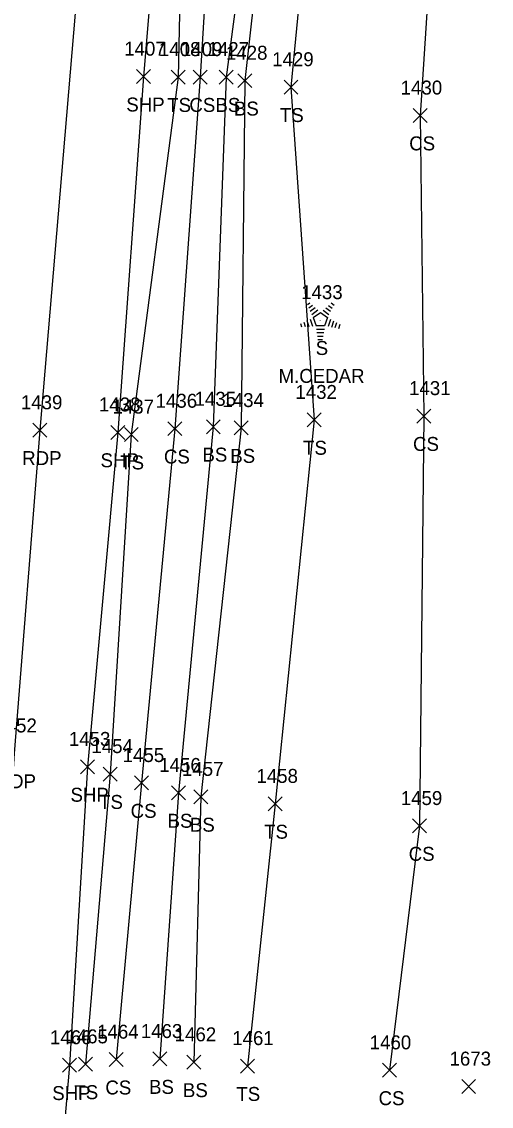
# Model space of a CAD drawing. Extents: x 1443960 to 1446865, y 610387 to 616706.
# Drawn here: x 1446592.3 to 1446659.6, y 610855.3 to 611010.8 of the extents above; entities that cross this region are included whole.
import ezdxf

# ---------------------------------------------------------------- set-up
doc = ezdxf.new("R2010")
doc.units = 0
for name, color, linetype in [('L_A', 7, 'Continuous'), ('L_C', 7, 'Continuous'), ('L_I', 7, 'Continuous'), ('L_TIC', 7, 'Continuous'), ('LELB', 7, 'Continuous'), ('LTC', 7, 'Continuous'), ('P_A', 7, 'Continuous'), ('P_I', 7, 'Continuous'), ('P_TIC', 7, 'Continuous'), ('PET', 7, 'Continuous'), ('PSP', 7, 'Continuous')]:
    doc.layers.add(name, color=color, linetype=linetype)

msp = doc.modelspace()

# ---------------------------------------------------------------- linework, layer by layer
at = {"layer": 'L_TIC'}
for points in [[(1446613.77, 611001.83), (1446615.77, 611003.83)], [(1446615.77, 611001.83), (1446613.77, 611003.83)], [(1446616.92, 611001.83), (1446618.92, 611003.83)], [(1446618.92, 611001.83), (1446616.92, 611003.83)], [(1446620.65, 611001.83), (1446622.65, 611003.83)], [(1446622.65, 611001.83), (1446620.65, 611003.83)], [(1446623.29, 611001.31), (1446625.29, 611003.31)], [(1446625.29, 611001.31), (1446623.29, 611003.31)], [(1446629.92, 611000.38), (1446631.92, 611002.38)], [(1446631.92, 611000.38), (1446629.92, 611002.38)], [(1446648.42, 610996.32), (1446650.42, 610998.32)], [(1446650.42, 610996.32), (1446648.42, 610998.32)], [(1446633.24, 610952.7), (1446635.24, 610954.7)], [(1446635.24, 610952.7), (1446633.24, 610954.7)], [(1446648.97, 610953.25), (1446650.97, 610955.25)], [(1446650.97, 610953.25), (1446648.97, 610955.25)], [(1446613.27, 610951.44), (1446615.27, 610953.44)], [(1446615.27, 610951.44), (1446613.27, 610953.44)], [(1446618.79, 610951.72), (1446620.79, 610953.72)], [(1446620.79, 610951.72), (1446618.79, 610953.72)], [(1446622.78, 610951.54), (1446624.78, 610953.54)], [(1446624.78, 610951.54), (1446622.78, 610953.54)], [(1446607.04, 610950.6), (1446609.04, 610952.6)], [(1446609.04, 610950.6), (1446607.04, 610952.6)], [(1446604.01, 610901.95), (1446606.01, 610903.95)], [(1446606.01, 610901.95), (1446604.01, 610903.95)], [(1446608.49, 610900.67), (1446610.49, 610902.67)], [(1446610.49, 610900.67), (1446608.49, 610902.67)], [(1446613.79, 610899.25), (1446615.79, 610901.25)], [(1446615.79, 610899.25), (1446613.79, 610901.25)], [(1446616.99, 610898.69), (1446618.99, 610900.69)], [(1446618.99, 610898.69), (1446616.99, 610900.69)], [(1446627.67, 610897.68), (1446629.67, 610899.68)], [(1446629.67, 610897.68), (1446627.67, 610899.68)], [(1446648.35, 610894.51), (1446650.35, 610896.51)], [(1446650.35, 610894.51), (1446648.35, 610896.51)], [(1446604.88, 610861.03), (1446606.88, 610863.03)], [(1446606.88, 610861.03), (1446604.88, 610863.03)], [(1446611.14, 610861.12), (1446613.14, 610863.12)], [(1446613.14, 610861.12), (1446611.14, 610863.12)], [(1446600.47, 610860.36), (1446602.47, 610862.36)], [(1446602.47, 610860.36), (1446600.47, 610862.36)], [(1446615.99, 610860.65), (1446617.99, 610862.65)], [(1446617.99, 610860.65), (1446615.99, 610862.65)], [(1446623.68, 610860.11), (1446625.68, 610862.11)], [(1446625.68, 610860.11), (1446623.68, 610862.11)], [(1446644.03, 610859.5), (1446646.03, 610861.5)], [(1446646.03, 610859.5), (1446644.03, 610861.5)], [(1446655.38, 610857.17), (1446657.38, 610859.17)], [(1446657.38, 610857.17), (1446655.38, 610859.17)]]:
    msp.add_lwpolyline(points, dxfattribs=at)
at = {"layer": 'LELB'}
for points in [[(1446830.28, 611016.53), (1446811.1, 611028.66), (1446776.07, 611047.22), (1446765.1, 611052.74), (1446718.13, 611075.14), (1446677.7, 611094.8), (1446645.56, 611110.93), (1446633.09, 611119.85), (1446623.05, 611121.28), (1446619.75, 611099.3), (1446617.85, 611081.96), (1446615.6, 611043.86), (1446614.77, 611002.83), (1446608.04, 610951.6), (1446605.01, 610902.95), (1446601.47, 610861.36)], [(1446829.25, 611014.38), (1446810.48, 611025.97), (1446776.26, 611044.05), (1446764.8, 611049.49), (1446716.62, 611070.84), (1446676.65, 611091.11), (1446643.97, 611105.98), (1446632.65, 611089.9), (1446628.97, 611091.61), (1446629.07, 611084.29), (1446632.07, 611081.47), (1446632.15, 611079.98), (1446631.66, 611078.24), (1446628.85, 611073.01), (1446626.96, 611043.36), (1446621.65, 611002.83), (1446619.79, 610952.72), (1446614.79, 610900.25), (1446612.14, 610862.12)], [(1446830.53, 611008.19), (1446807.85, 611021.07), (1446773.55, 611038.49), (1446762.29, 611043.61), (1446752.72, 611051.34), (1446711.65, 611062.43), (1446674.23, 611080.27), (1446638.75, 611091.24), (1446639.39, 611078.57), (1446637.85, 611065.45), (1446634.87, 611042.47), (1446630.92, 611001.38), (1446634.24, 610953.7), (1446628.67, 610898.68), (1446624.68, 610861.11)], [(1446632.65, 611089.9), (1446635.11, 611083.16), (1446632.02, 611073.63), (1446628.9, 611043.3), (1446624.29, 611002.31), (1446623.78, 610952.54), (1446617.99, 610899.69), (1446616.99, 610861.65)], [(1446617.85, 611081.96), (1446622.59, 611079.29), (1446620.41, 611043.65), (1446617.92, 611002.83), (1446614.27, 610952.44), (1446609.49, 610901.67), (1446605.88, 610862.03)], [(1446826.78, 610994.51), (1446805.32, 611011.95), (1446772.11, 611030.78), (1446756.49, 611034.3), (1446751.93, 611036.39), (1446704.53, 611051.58), (1446668.04, 611061.39), (1446654.45, 611063.68), (1446651.98, 611036.37), (1446649.42, 610997.32), (1446649.97, 610954.25), (1446649.35, 610895.51), (1446645.03, 610860.5)]]:
    msp.add_lwpolyline(points, dxfattribs=at)
at = {"layer": 'LTC'}
for p, q in [((1446633.27, 610970.21), (1446633.62, 610970.47)), ((1446633.48, 610969.75), (1446634.01, 610970.13)), ((1446636.3, 610970.1), (1446636.84, 610969.7)), ((1446636.67, 610970.45), (1446637.09, 610970.15)), ((1446633.69, 610969.28), (1446634.39, 610969.79)), ((1446633.9, 610968.81), (1446634.78, 610969.45)), ((1446634.12, 610968.36), (1446635.13, 610969.09)), ((1446635.13, 610969.09), (1446636.13, 610968.37)), ((1446635.55, 610969.41), (1446636.36, 610968.82)), ((1446635.92, 610969.76), (1446636.6, 610969.26)), ((1446632.3, 610967.49), (1446632.45, 610967.02)), ((1446632.76, 610967.71), (1446632.97, 610967.06)), ((1446633.21, 610967.92), (1446633.48, 610967.09)), ((1446633.67, 610968.14), (1446634, 610967.12)), ((1446634.12, 610968.36), (1446634.51, 610967.17)), ((1446635.74, 610967.17), (1446634.51, 610967.17)), ((1446636.13, 610968.37), (1446635.74, 610967.17)), ((1446636.57, 610968.1), (1446636.23, 610967.06)), ((1446637.01, 610967.85), (1446636.72, 610966.96)), ((1446637.46, 610967.6), (1446637.22, 610966.87)), ((1446637.9, 610967.35), (1446637.71, 610966.77)), ((1446635.7, 610966.67), (1446634.56, 610966.67)), ((1446635.62, 610966.17), (1446634.63, 610966.17)), ((1446635.53, 610965.67), (1446634.7, 610965.67)), ((1446635.45, 610965.17), (1446634.77, 610965.17))]:
    msp.add_line(p, q, dxfattribs=at)
at = {"layer": 'P_TIC'}
for points in [[(1446608.79, 611001.89), (1446610.79, 611003.89)], [(1446610.79, 611001.89), (1446608.79, 611003.89)], [(1446593.91, 610951.22), (1446595.91, 610953.22)], [(1446595.91, 610951.22), (1446593.91, 610953.22)], [(1446605.09, 610950.91), (1446607.09, 610952.91)], [(1446607.09, 610950.91), (1446605.09, 610952.91)], [(1446600.78, 610902.98), (1446602.78, 610904.98)], [(1446602.78, 610902.98), (1446600.78, 610904.98)], [(1446598.17, 610860.23), (1446600.17, 610862.23)], [(1446600.17, 610860.23), (1446598.17, 610862.23)]]:
    msp.add_lwpolyline(points, dxfattribs=at)
at = {"layer": 'PET'}
msp.add_lwpolyline([(1446610.71, 611136.75), (1446609.78, 611124.94), (1446606.08, 611083.4), (1446602.84, 611045.86), (1446594.91, 610952.22), (1446591.25, 610905.91), (1446588.27, 610860.89), (1446582.86, 610791.01), (1446578.03, 610732.6), (1446571.55, 610656.07), (1446565.6, 610584.23)], dxfattribs=at)
at = {"layer": 'PSP'}
msp.add_lwpolyline([(1446619.04, 611132.42), (1446618.93, 611131.58), (1446619.27, 611123.52), (1446616.01, 611082.04), (1446613.23, 611044.06), (1446609.79, 611002.89), (1446606.09, 610951.91), (1446601.78, 610903.98), (1446599.17, 610861.23), (1446593.05, 610789.59), (1446588.39, 610733.33), (1446581.3, 610654.53), (1446575.41, 610584.21)], dxfattribs=at)

# ---------------------------------------------------------------- texts
at = {"layer": 'L_A'}
for s, p in [('TS', (1446613.18, 610997.83)), ('CS', (1446616.36, 610997.83)), ('BS', (1446620.09, 610997.83)), ('BS', (1446622.74, 610997.31)), ('TS', (1446629.33, 610996.38)), ('CS', (1446647.86, 610992.32)), ('S', (1446634.46, 610963)), ('CS', (1446648.41, 610949.25)), ('BS', (1446618.23, 610947.72)), ('TS', (1446632.65, 610948.7)), ('TS', (1446606.45, 610946.6)), ('CS', (1446612.71, 610947.44)), ('BS', (1446622.22, 610947.54)), ('TS', (1446603.42, 610897.95)), ('CS', (1446607.94, 610896.67)), ('BS', (1446613.23, 610895.25)), ('BS', (1446616.43, 610894.69)), ('TS', (1446627.07, 610893.68)), ('CS', (1446647.79, 610890.51)), ('TS', (1446599.88, 610856.36)), ('CS', (1446604.32, 610857.03)), ('BS', (1446610.58, 610857.12)), ('BS', (1446615.43, 610856.65)), ('TS', (1446623.09, 610856.11)), ('CS', (1446643.47, 610855.5))]:
    msp.add_text(s, height=2, dxfattribs=at).set_placement(p)
at = {"layer": 'L_C'}
msp.add_text('M.CEDAR', height=2, dxfattribs=at).set_placement((1446629.13, 610959))
at = {"layer": 'L_I'}
for s, p in [('1408', (1446612, 611005.83)), ('1409', (1446615.14, 611005.83)), ('1427', (1446618.96, 611005.83)), ('1428', (1446621.6, 611005.31)), ('1429', (1446628.22, 611004.38)), ('1430', (1446646.64, 611000.32)), ('1433', (1446632.38, 610971)), ('1431', (1446647.84, 610957.25)), ('1435', (1446617.1, 610955.72)), ('1434', (1446621.09, 610955.54)), ('1432', (1446631.55, 610956.7)), ('1437', (1446605.34, 610954.6)), ('1436', (1446611.52, 610955.44)), ('1454', (1446602.32, 610905.95)), ('1455', (1446606.8, 610904.67)), ('1456', (1446612.04, 610903.25)), ('1457', (1446615.3, 610902.69)), ('1458', (1446625.97, 610901.68)), ('1459', (1446646.65, 610898.51)), ('1465', (1446598.73, 610864.36)), ('1464', (1446603.14, 610865.03)), ('1463', (1446609.4, 610865.12)), ('1462', (1446614.25, 610864.65)), ('1461', (1446622.5, 610864.11)), ('1460', (1446642.2, 610863.5)), ('1673', (1446653.64, 610861.17))]:
    msp.add_text(s, height=2, dxfattribs=at).set_placement(p)
at = {"layer": 'LTC'}
msp.add_text('.', height=1.04, rotation=270, dxfattribs=at).set_placement((1446635.02, 610968.11))
at = {"layer": 'P_A'}
for s, p in [('SHP', (1446607.32, 610997.89)), ('RDP', (1446592.4, 610947.22)), ('SHP', (1446603.63, 610946.91)), ('RDP', (1446588.73, 610900.91)), ('SHP', (1446599.32, 610898.98)), ('SHP', (1446596.71, 610856.23))]:
    msp.add_text(s, height=2, dxfattribs=at).set_placement(p)
at = {"layer": 'P_I'}
for s, p in [('1407', (1446607.02, 611005.89)), ('1439', (1446592.21, 610955.22)), ('1438', (1446603.4, 610954.91)), ('1452', (1446588.55, 610908.91)), ('1453', (1446599.09, 610906.98)), ('1466', (1446596.38, 610864.23))]:
    msp.add_text(s, height=2, dxfattribs=at).set_placement(p)

doc.saveas('drawing.dxf')
